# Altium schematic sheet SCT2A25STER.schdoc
size 127 x 101 mm
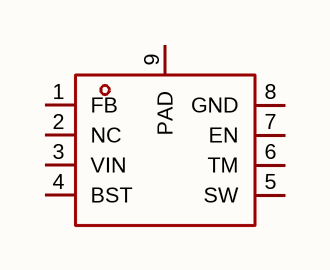
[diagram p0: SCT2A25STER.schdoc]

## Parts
U?  sct2a25ster  [ESOP-8_L4.9-W3.9-P1.27-LS6.0-BL-EP]  (value not drawn)

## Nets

Not connected (* = marked no-connect by the designer): U? 1(FB) 2(NC) 3(VIN) 4(BST) 5(SW) 6(TM) 7(EN) 8(GND) 9(PAD)

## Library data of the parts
U? = sct2a25ster: 功能类型:降压型;工作电压:5.5V~100V;输出电压:1.2V~30V;输出电流:2A;输出类型:可调;; Manufacturer: SCT(芯洲科技); AddInBom: yes; ModelId: d3e00daa36c445139c055a3b9efb85d2; ModelName: ESOP-8_L4.9-W3.9-H1.6-LS6.0-P1.27; ModelTransform: 240.157,192.913,0,90,0,0,0,0,0; Function: 降压型; Output Current: 2A; Frequency - Switching: 300kHz; Synchronous Rectifier: 否; Number of Outputs: 1; Topology: 降压式; Quiescent Current: 135uA; Switch tube (built-in/external): 内置; Output Type: 可调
